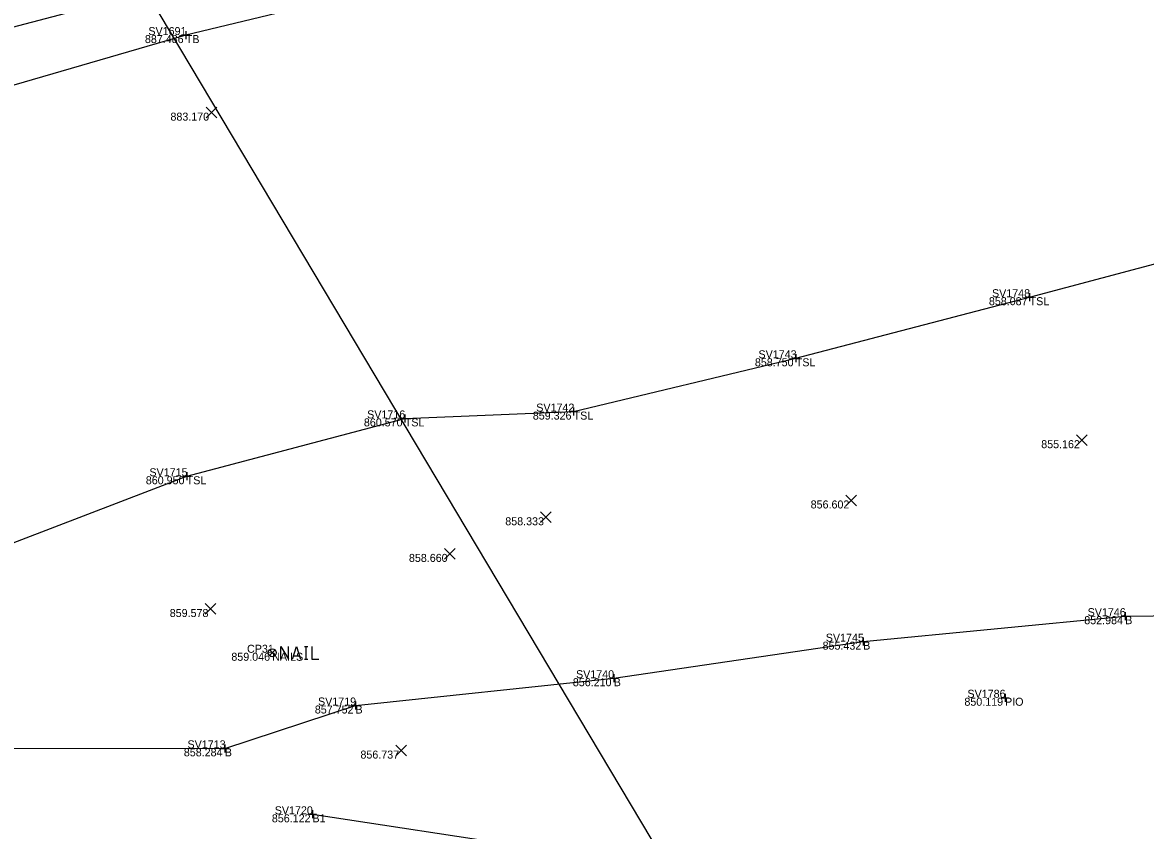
# Model space of a CAD drawing. Extents: x 2125299 to 2129212, y 713100 to 714300.
# Drawn here: x 2127665 to 2127805.3, y 713670.1 to 713771.1 of the extents above; entities that cross this region are included whole.
import ezdxf

# ---------------------------------------------------------------- set-up
doc = ezdxf.new("R2010")
doc.units = 0
for name, color, linetype in [('DR_X_Storm_Sewer', 7, 'Continuous'), ('RW_P_Esmt_TMP', 7, 'Continuous'), ('RW_X_CL_100_Cardinal_Points', 7, 'Continuous'), ('RW_X_Esmt_CH', 7, 'Continuous'), ('RW_X_Fee_WL', 7, 'Continuous'), ('SC_Scratch1', 7, 'Continuous'), ('SV_X_Break_Lines', 7, 'Continuous'), ('SV_X_Mon_Cells_Found', 7, 'Continuous'), ('SV_X_Text_Elevation', 7, 'Continuous'), ('SV_X_Text_Name', 7, 'Continuous'), ('SV_X_Toe_of_Slope', 7, 'Continuous'), ('SV_X_Top_of_Bank', 7, 'Continuous')]:
    doc.layers.add(name, color=color, linetype=linetype)

msp = doc.modelspace()

# ---------------------------------------------------------------- linework, layer by layer
at = {"layer": 'DR_X_Storm_Sewer'}
msp.add_line((2127551.46, 713991.15), (2127754.53, 713650.69), dxfattribs=at)
at = {"layer": 'RW_X_CL_100_Cardinal_Points'}
for p, q in [((2127787.78, 713687.21), (2127787.78, 713686.21)), ((2127787.28, 713686.71), (2127788.28, 713686.71)), ((2127787.78, 713686.71), (2127787.78, 713686.71))]:
    msp.add_line(p, q, dxfattribs=at)
at = {"layer": 'SC_Scratch1'}
msp.add_lwpolyline([(2127133.38, 713627.43), (2127166.26, 713637.18), (2127280.77, 713668.85), (2127395.3, 713699.47), (2127509.42, 713729.99), (2127750.89, 713793.4), (2127929.41, 713841.22)], dxfattribs=at)
at = {"layer": 'SV_X_Break_Lines'}
for points in [[(2127616.18, 713671.15), (2127652.31, 713680.4), (2127690.28, 713680.39), (2127706.61, 713685.74), (2127738.88, 713689.15), (2127770.05, 713693.72), (2127802.8, 713696.9), (2127834.4, 713697.26), (2127862.23, 713700.52)], [(2127701.23, 713672.15), (2127728.04, 713668.09)]]:
    msp.add_lwpolyline(points, dxfattribs=at)
at = {"layer": 'SV_X_Mon_Cells_Found'}
for p, q in [((2127685.41, 713770), (2127685.41, 713769)), ((2127684.91, 713769.5), (2127685.91, 713769.5)), ((2127685.41, 713769.5), (2127685.41, 713769.5)), ((2127790.85, 713737.25), (2127790.85, 713736.25)), ((2127790.35, 713736.75), (2127791.35, 713736.75)), ((2127790.85, 713736.75), (2127790.85, 713736.75)), ((2127761.13, 713729.12), (2127762.13, 713729.12)), ((2127761.63, 713729.62), (2127761.63, 713728.62)), ((2127761.63, 713729.12), (2127761.63, 713729.12)), ((2127712.77, 713722.11), (2127712.77, 713721.11)), ((2127733.37, 713722.46), (2127734.37, 713722.46)), ((2127733.87, 713722.96), (2127733.87, 713721.96)), ((2127733.87, 713722.46), (2127733.87, 713722.46)), ((2127712.27, 713721.61), (2127713.27, 713721.61)), ((2127712.77, 713721.61), (2127712.77, 713721.61)), ((2127685.52, 713714.88), (2127685.52, 713713.88)), ((2127685.02, 713714.38), (2127686.02, 713714.38)), ((2127685.52, 713714.38), (2127685.52, 713714.38)), ((2127802.3, 713696.9), (2127803.3, 713696.9)), ((2127802.8, 713697.4), (2127802.8, 713696.4)), ((2127802.8, 713696.9), (2127802.8, 713696.9)), ((2127770.05, 713694.22), (2127770.05, 713693.22)), ((2127769.55, 713693.72), (2127770.55, 713693.72)), ((2127770.05, 713693.72), (2127770.05, 713693.72)), ((2127738.88, 713689.65), (2127738.88, 713688.65)), ((2127738.38, 713689.15), (2127739.38, 713689.15)), ((2127738.88, 713689.15), (2127738.88, 713689.15)), ((2127706.11, 713685.74), (2127707.11, 713685.74)), ((2127706.61, 713686.24), (2127706.61, 713685.24)), ((2127706.61, 713685.74), (2127706.61, 713685.74)), ((2127689.78, 713680.39), (2127690.78, 713680.39)), ((2127690.28, 713680.89), (2127690.28, 713679.89)), ((2127690.28, 713680.39), (2127690.28, 713680.39)), ((2127700.73, 713672.15), (2127701.73, 713672.15)), ((2127701.23, 713672.65), (2127701.23, 713671.65)), ((2127701.23, 713672.15), (2127701.23, 713672.15))]:
    msp.add_line(p, q, dxfattribs=at)
at = {"layer": 'SV_X_Text_Elevation'}
for p, q in [((2127687.94, 713759.14), (2127689.27, 713760.48)), ((2127687.94, 713760.48), (2127689.27, 713759.14)), ((2127796.7, 713718.22), (2127798.04, 713719.56)), ((2127796.7, 713719.56), (2127798.04, 713718.22)), ((2127767.89, 713710.69), (2127769.23, 713712.02)), ((2127767.89, 713712.02), (2127769.23, 713710.69)), ((2127729.73, 713708.59), (2127731.06, 713709.93)), ((2127729.73, 713709.93), (2127731.06, 713708.59)), ((2127717.74, 713704.01), (2127719.07, 713705.35)), ((2127717.74, 713705.35), (2127719.07, 713704.01)), ((2127687.83, 713697.14), (2127689.17, 713698.47)), ((2127687.83, 713698.47), (2127689.17, 713697.14)), ((2127711.66, 713679.44), (2127713, 713680.77)), ((2127711.66, 713680.77), (2127713, 713679.44))]:
    msp.add_line(p, q, dxfattribs=at)
at = {"layer": 'SV_X_Text_Name'}
for p, q in [((2127695.85, 713692.68), (2127696.56, 713691.97)), ((2127695.85, 713691.97), (2127696.56, 713692.68))]:
    msp.add_line(p, q, dxfattribs=at)
for points in [[(2127697.29, 713691.52), (2127697.29, 713693.12), (2127698.24, 713691.52), (2127698.24, 713693.12)], [(2127698.74, 713691.52), (2127699.25, 713693.12), (2127699.74, 713691.52)], [(2127700.24, 713693.12), (2127700.65, 713693.12)], [(2127700.44, 713691.52), (2127700.44, 713693.12)], [(2127701.15, 713693.12), (2127701.15, 713691.52), (2127702.02, 713691.52)], [(2127699.61, 713691.89), (2127698.87, 713691.89)], [(2127700.24, 713691.52), (2127700.65, 713691.52)]]:
    msp.add_lwpolyline(points, dxfattribs=at)
msp.add_circle((2127696.21, 713692.33), 0.5, dxfattribs=at)
at = {"layer": 'SV_X_Toe_of_Slope'}
msp.add_lwpolyline([(2127560.57, 713676.96), (2127620.08, 713691.3), (2127651.95, 713701.51), (2127685.52, 713714.38), (2127712.77, 713721.61), (2127733.87, 713722.46), (2127761.63, 713729.12), (2127790.85, 713736.75), (2127822.01, 713745.03), (2127854.59, 713754.33)], dxfattribs=at)
at = {"layer": 'SV_X_Top_of_Bank'}
msp.add_lwpolyline([(2127920.85, 713834.18), (2127873.9, 713818.39), (2127828.31, 713807.04), (2127782.81, 713794.43), (2127731.94, 713780.7), (2127685.41, 713769.5), (2127638.8, 713755.97), (2127588.05, 713743.29)], dxfattribs=at)

# ---------------------------------------------------------------- texts
at = {"layer": 'RW_P_Esmt_TMP'}
for s, p in [('TB', (2127685.41, 713768.5)), ('TSL', (2127790.85, 713735.75)), ('TSL', (2127761.63, 713728.12)), ('TSL', (2127733.87, 713721.46)), ('TSL', (2127712.77, 713720.61)), ('TSL', (2127685.52, 713713.38)), ('B', (2127802.8, 713695.9)), ('NAILS', (2127696.21, 713691.33)), ('B', (2127770.05, 713692.72)), ('B', (2127738.88, 713688.15)), ('PIO', (2127787.78, 713685.71)), ('B', (2127706.61, 713684.74)), ('B', (2127690.28, 713679.39)), ('B1', (2127701.23, 713671.15))]:
    msp.add_text(s, height=1, dxfattribs=at).set_placement(p)
at = {"layer": 'RW_X_Esmt_CH'}
for s, p in [('SV1691', (2127680.73, 713769.5)), ('SV1748', (2127786.15, 713736.75)), ('SV1743', (2127756.97, 713729.12)), ('SV1742', (2127729.2, 713722.46)), ('SV1716', (2127708.07, 713721.61)), ('SV1715', (2127680.86, 713714.38)), ('SV1746', (2127798.1, 713696.9)), ('SV1745', (2127765.38, 713693.72)), ('CP31', (2127693.06, 713692.33)), ('SV1740', (2127734.17, 713689.15)), ('SV1719', (2127701.93, 713685.74)), ('SV1786', (2127783.08, 713686.71)), ('SV1713', (2127685.62, 713680.39)), ('SV1720', (2127696.52, 713672.15))]:
    msp.add_text(s, height=1, dxfattribs=at).set_placement(p)
at = {"layer": 'RW_X_Fee_WL'}
for s, p in [('887.486', (2127680.3, 713768.5)), ('883.170', (2127683.49, 713758.81)), ('858.087', (2127785.76, 713735.75)), ('858.750', (2127756.52, 713728.12)), ('859.326', (2127728.77, 713721.46)), ('860.570', (2127707.66, 713720.61)), ('855.162', (2127792.3, 713717.89)), ('860.950', (2127680.41, 713713.38)), ('856.602', (2127763.49, 713710.36)), ('858.333', (2127725.33, 713708.26)), ('858.660', (2127713.29, 713703.68)), ('859.578', (2127683.4, 713696.8)), ('852.984', (2127797.68, 713695.9)), ('855.432', (2127764.98, 713692.72)), ('859.046', (2127691.1, 713691.33)), ('856.210', (2127733.77, 713688.15)), ('850.119', (2127782.7, 713685.71)), ('857.752', (2127701.53, 713684.74)), ('858.284', (2127685.16, 713679.39)), ('856.737', (2127707.23, 713679.11)), ('856.122', (2127696.16, 713671.15))]:
    msp.add_text(s, height=1, dxfattribs=at).set_placement(p)

doc.saveas('drawing.dxf')
